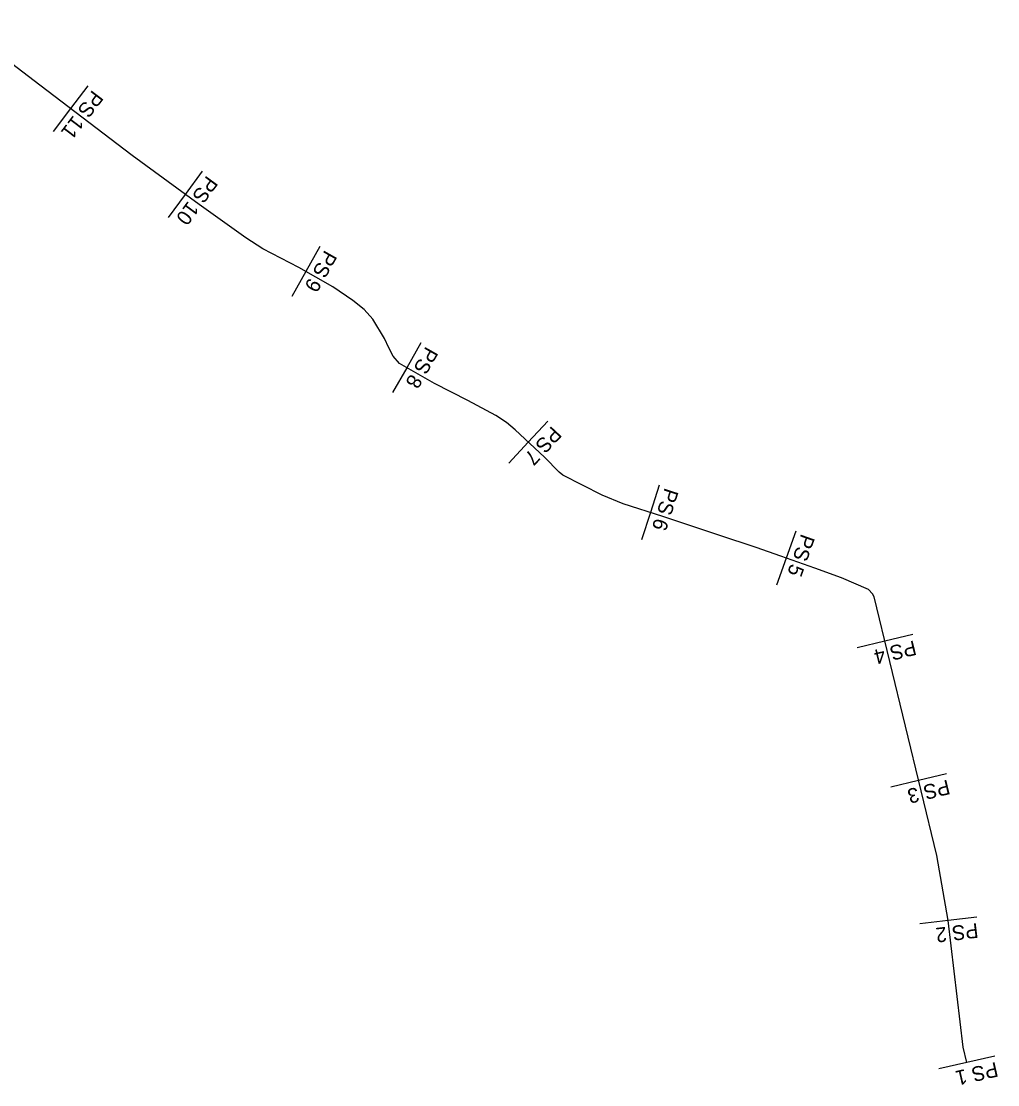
# Model space of a CAD drawing. Extents: x -844670 to -843025, y -997533 to -995513.
# Drawn here: x -843691.4 to -843350.6, y -997533.2 to -997161.9 of the extents above; entities that cross this region are included whole.
import ezdxf

# ---------------------------------------------------------------- set-up
doc = ezdxf.new("R2010")
doc.units = 0
doc.layers.add('Osa', color=7, linetype='Continuous')
doc.layers.add('Řezy', color=7, linetype='Continuous')

msp = doc.modelspace()

# ---------------------------------------------------------------- linework, layer by layer
at = {"layer": 'Osa'}
msp.add_lwpolyline([(-843361.41, -997525.4), (-843362.64, -997520.02), (-843367.9, -997475.79), (-843371.92, -997453.18), (-843393.72, -997362.81), (-843394.27, -997361.8), (-843395.73, -997360.23), (-843405.12, -997356.15), (-843414.51, -997352.84), (-843426.28, -997348.67), (-843434.95, -997345.64), (-843447.93, -997341.27), (-843467.56, -997334.81), (-843481.31, -997330.35), (-843488.74, -997327.35), (-843502.42, -997320.34), (-843503.72, -997319.36), (-843508.85, -997314.12), (-843519.09, -997304.58), (-843522.13, -997301.97), (-843525.76, -997299.52), (-843535.54, -997294.28), (-843547.18, -997288.35), (-843559.45, -997281.39), (-843561.6, -997278.77), (-843563.2, -997275.89), (-843564.61, -997272.67), (-843568.72, -997265.95), (-843571.74, -997262.55), (-843575.66, -997259.4), (-843582.66, -997254.57), (-843594.61, -997247.84), (-843607.17, -997241.3), (-843613.08, -997237.56), (-843629.39, -997225.89), (-843652.73, -997208.73), (-843685.02, -997184.17), (-843714.34, -997161.92)], dxfattribs=at)
at = {"layer": 'Řezy'}
for points in [[(-843668.17, -997184.43), (-843674.22, -997192.39), (-843680.27, -997200.34)], [(-843628.28, -997214.29), (-843634.2, -997222.35), (-843640.12, -997230.41)], [(-843587.25, -997240.51), (-843592.15, -997249.23), (-843597.06, -997257.94)], [(-843551.95, -997274.15), (-843556.88, -997282.84), (-843561.82, -997291.54)], [(-843507.66, -997301.56), (-843514.48, -997308.87), (-843521.3, -997316.19)], [(-843468.75, -997323.91), (-843471.84, -997333.42), (-843474.92, -997342.93)], [(-843421.09, -997339.9), (-843424.43, -997349.32), (-843427.78, -997358.75)], [(-843380.25, -997376), (-843389.97, -997378.35), (-843399.69, -997380.69)], [(-843368.53, -997424.61), (-843378.25, -997426.95), (-843387.97, -997429.3)], [(-843357.96, -997474.66), (-843367.89, -997475.84), (-843377.82, -997477.03)], [(-843351.66, -997523.17), (-843361.41, -997525.4), (-843371.16, -997527.62)]]:
    msp.add_lwpolyline(points, dxfattribs=at)

# ---------------------------------------------------------------- texts
for s, rotation, p in [('PS 11', 232.7382, (-843666.53, -997185.67)), ('PS 10', 233.6909, (-843626.62, -997215.51)), ('PS 9', 240.636, (-843585.46, -997241.52)), ('PS 8', 240.4288, (-843550.16, -997275.16)), ('PS 7', 227.0258, (-843506.16, -997302.96)), ('PS 6', 252.0349, (-843466.8, -997324.54)), ('PS 5', 250.4588, (-843419.16, -997340.59)), ('PS 4', 193.5624, (-843379.77, -997378)), ('PS 3', 193.5624, (-843368.04, -997426.6)), ('PS 2', 186.7827, (-843357.72, -997476.7)), ('PS 1', 192.8273, (-843351.2, -997525.18))]:
    msp.add_text(s, height=5.132, rotation=rotation, dxfattribs=at).set_placement(p)

doc.saveas('drawing.dxf')
